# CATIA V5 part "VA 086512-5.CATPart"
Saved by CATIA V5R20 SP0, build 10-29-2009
Part number: VA 086512-5
Revision: ANY
Definition: UNKNOWN
Nomenclature: VA 086512-5
Source: Unknown
Bounding box of the stored display mesh (mm): x -3.329 to 3.329, y 0.1 to 1.2, z -3.5 to 3.5
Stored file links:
  C:\Users\Utente\Desktop\IO LAVORO\3D X SITO CF\CUMSA\3D files VA\VA 086512\VA 086512-5.CATPart
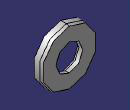
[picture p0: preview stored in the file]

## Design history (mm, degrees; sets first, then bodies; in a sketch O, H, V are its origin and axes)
Body1 "Cortar-Extruir1" (main body)
  Solid1: solid without history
